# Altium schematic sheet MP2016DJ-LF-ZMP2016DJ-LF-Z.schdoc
size 127 x 101 mm
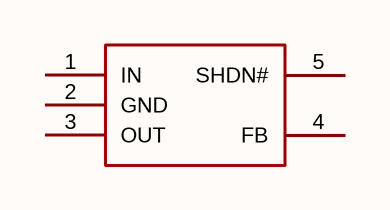
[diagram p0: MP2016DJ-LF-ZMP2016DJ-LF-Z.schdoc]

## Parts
U?  mp2016dj-lf-z  [TSOT-23-5_L2.9-W1.6-P0.95-LS2.8-BR]  (value not drawn)

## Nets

Not connected (* = marked no-connect by the designer): U? 1(IN) 2(GND) 3(OUT) 4(FB) 5(SHDN#)

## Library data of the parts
U? = mp2016dj-lf-z: 输出极性:正极;工作电压:42V;输出电压:1.2V~40V;输出电流:30mA;电源纹波抑制比(PSRR):65dB;输出类型:可调;; Manufacturer: MPS(芯源); AddInBom: yes; ModelId: b5108020abe84f7bb0f3c398b43b6e0b; ModelName: TSOT-23-5_L2.9-W1.6-H1.00-LS2.8-P0.95; ModelTransform: 110.45568,114.173,0,180,0,0,0,0,0; Output Configuration: 正极; Voltage - Supply: 42V; Output Current: 30mA; Power Supply Rejection Ratio (PSRR): 65dB; Voltage Dropout: 700mV@(30mA); standby current: 12uA; Output Type: 可调; Number of Outputs: 1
